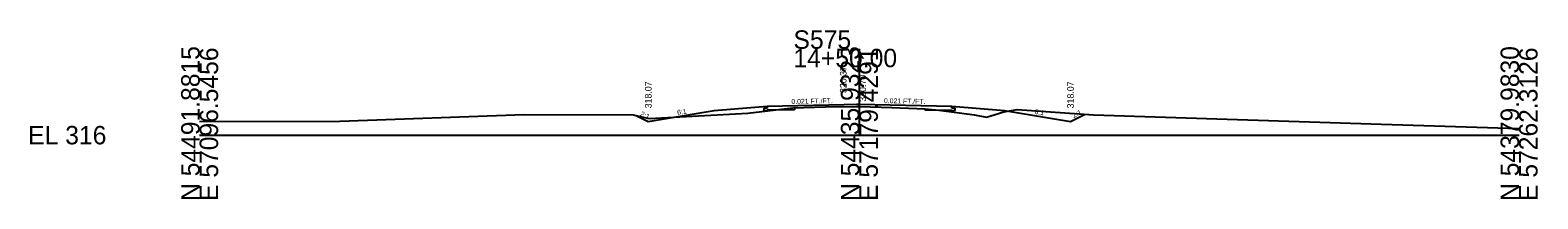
# Model space of a CAD drawing. Extents: x 10119 to 10347, y 94341 to 98867.
# Drawn here: x 10118.6 to 10347.2, y 98341.1 to 98366.8 of the extents above; entities that cross this region are included whole.
import ezdxf

# ---------------------------------------------------------------- set-up
doc = ezdxf.new("R2010")
doc.units = 0
for name, color, linetype in [('Level 10', 7, 'Continuous'), ('Level 11', 7, 'Continuous'), ('Level 12', 7, 'Continuous'), ('Level 32', 7, 'Continuous'), ('Level 33', 7, 'Continuous'), ('Level 59', 7, 'Continuous'), ('Level 6', 7, 'Continuous'), ('Level 60', 7, 'Continuous'), ('Level 63', 7, 'Continuous'), ('Level 7', 7, 'Continuous')]:
    doc.layers.add(name, color=color, linetype=linetype)

msp = doc.modelspace()

# ---------------------------------------------------------------- linework, layer by layer
at = {"layer": 'Level 11'}
for p, q in [((10230.31, 98354.93), (10229.81, 98354.91)), ((10229.81, 98354.91), (10229.81, 98354.57)), ((10229.81, 98354.57), (10230.31, 98354.59)), ((10230.31, 98355.22), (10230.31, 98354.93)), ((10258.31, 98354.93), (10258.31, 98355.22)), ((10258.81, 98354.91), (10258.31, 98354.93)), ((10258.31, 98354.59), (10258.81, 98354.57)), ((10258.81, 98354.57), (10258.81, 98354.91))]:
    msp.add_line(p, q, dxfattribs=at)
at = {"layer": 'Level 12'}
for p, q in [((10234.47, 98354.67), (10230.31, 98354.59)), ((10234.47, 98354.97), (10234.47, 98354.67)), ((10254.23, 98354.81), (10254.23, 98354.67)), ((10254.23, 98354.67), (10258.31, 98354.59))]:
    msp.add_line(p, q, dxfattribs=at)
at = {"layer": 'Level 59'}
for p, q in [((10230.31, 98355.22), (10244.31, 98355.51)), ((10244.31, 98355.51), (10258.31, 98355.22))]:
    msp.add_line(p, q, dxfattribs=at)
at = {"layer": 'Level 6'}
for p, q in [((10222.31, 98354.55), (10230.31, 98355.22)), ((10258.31, 98355.22), (10266.31, 98354.55))]:
    msp.add_line(p, q, dxfattribs=at)
at = {"layer": 'Level 60'}
for p, q in [((10165.54, 98352.91), (10193.49, 98353.94)), ((10193.49, 98353.94), (10210.03, 98353.9)), ((10210.03, 98353.9), (10212.46, 98353.33)), ((10212.46, 98353.33), (10227.41, 98354.13)), ((10227.41, 98354.13), (10234.2, 98354.97)), ((10234.2, 98354.97), (10239.19, 98355.11)), ((10239.19, 98355.11), (10244.31, 98355.18)), ((10244.31, 98355.18), (10249.23, 98354.99)), ((10249.23, 98354.99), (10254.28, 98354.81)), ((10254.28, 98354.81), (10256.38, 98354.61)), ((10256.38, 98354.61), (10261.74, 98353.92)), ((10261.74, 98353.92), (10263.57, 98353.53)), ((10263.57, 98353.53), (10266.19, 98354.35)), ((10266.19, 98354.35), (10268.23, 98354.72)), ((10268.23, 98354.72), (10279.78, 98353.89)), ((10279.78, 98353.89), (10323.48, 98352.5)), ((10144.31, 98352.86), (10165.54, 98352.91)), ((10323.48, 98352.5), (10344.31, 98351.81))]:
    msp.add_line(p, q, dxfattribs=at)
at = {"layer": 'Level 63'}
for p, q in [((10244.31, 98350.81), (10244.31, 98363.93)), ((10144.31, 98350.81), (10244.31, 98350.81)), ((10244.31, 98350.81), (10344.31, 98350.81))]:
    msp.add_line(p, q, dxfattribs=at)
at = {"layer": 'Level 7'}
for p, q in [((10210.5, 98353.79), (10212.31, 98352.88)), ((10212.31, 98352.88), (10222.31, 98354.55)), ((10266.31, 98354.55), (10276.31, 98352.88)), ((10276.31, 98352.88), (10278.52, 98353.98))]:
    msp.add_line(p, q, dxfattribs=at)

# ---------------------------------------------------------------- texts
at = {"layer": 'Level 10'}
msp.add_text('320.37', height=1, rotation=90, dxfattribs=at).set_placement((10242.36, 98357.21))
at = {"layer": 'Level 32'}
for s, rotation, p in [('0.021 FT./FT.', 1.1916, (10234.02, 98355.54)), ('0.021 FT./FT.', 358.8084, (10248.03, 98355.68)), ('2:1', 333.435, (10211.01, 98353.81)), ('6:1', 9.4623, (10216.75, 98353.87)), ('6:1', 350.5377, (10270.83, 98354.05)), ('2:1', 26.5651, (10276.8, 98353.4))]:
    msp.add_text(s, height=0.75, rotation=rotation, dxfattribs=at).set_placement(p)
at = {"layer": 'Level 33'}
for p in [(10212.81, 98354.88), (10276.81, 98354.88)]:
    msp.add_text('318.07', height=1, rotation=90, dxfattribs=at).set_placement(p)
at = {"layer": 'Level 59'}
msp.add_text(' 320.70', height=1, rotation=90, dxfattribs=at).set_placement((10245.31, 98355.51))
at = {"layer": 'Level 63'}
for s, p in [('S575', (10234.32, 98363.93)), ('14+50.00', (10234.31, 98361.13)), ('EL 316', (10118.31, 98349.41))]:
    msp.add_text(s, height=2.8, dxfattribs=at).set_placement(p)
for s, p in [('N 54491.8815', (10144.31, 98340.81)), ('E 57096.5456', (10147.11, 98340.81)), ('N 54435.9323', (10244.31, 98340.81)), ('E 57179.4291', (10247.11, 98340.81)), ('N 54379.9830', (10344.31, 98340.81)), ('E 57262.3126', (10347.11, 98340.81))]:
    msp.add_text(s, height=2.8, rotation=90, dxfattribs=at).set_placement(p)

doc.saveas('drawing.dxf')
